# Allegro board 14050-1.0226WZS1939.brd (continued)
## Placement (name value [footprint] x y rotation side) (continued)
R144  100KR2J-1-GP  [R402H16]  42.58 25.78 0 top
R152  10KR2J-3-GP  [R402H16]  82.84 140.84 90 top
R154  10KR2J-3-GP  [R402H16]  71.66 141.86 270 top
R159  10KR2J-3-GP  [R402H16]  83.47 137.16 90 top
R160  10KR2J-3-GP  [R402H16]  71.66 140.84 90 top
R162  2K2R2J-2-GP  [R402H16]  82.33 143.51 0 top
R163  10KR2J-3-GP  [R402H16]  130.34 129.29 90 bottom
R165  10KR2J-3-GP  [R402H16]  131.86 128.78 0 bottom
R171  470KR2F-GP  [R402H16]  57.56 144.27 0 top
R172  1MR2J-1-GP  [R402H16]  57.18 138.56 90 top
R174  0R0402-PAD-2-GP  [0R0402-PAD-1]  55.28 139.57 270 top
R175  10KR2J-3-GP  [R402H16]  57.18 139.57 270 top
R178  1KR2J-1-GP  [R402H16]  49.44 136.78 270 top
R179  100KR2J-1-GP  [R402H16]  56.04 144.78 270 top
R181  100KR2J-1-GP  [R402H16]  56.04 143.76 90 top
R183  -  [0R0805-PAD]  7.53 190.88 0 bottom
R184  10KR2J-3-GP  [R402H16]  153.07 109.6 270 top
R185  -  [0R0805-PAD]  5.49 190.88 0 bottom
R202  2K1R2F-GP  [R402H16]  48.04 114.05 0 top
R203  2K1R2F-GP  [R402H16]  49.21 114.02 180 top
R205  0R0402-PAD-2-GP  [0R0402-PAD-1]  157.64 88.52 90 top
R206  0R2J-2-GP  [R402H16]  162.21 86.87 270 top
R207  0R0402-PAD-2-GP  [0R0402-PAD-1]  165.44 87.05 0 top
R208  47KR2F-GP  [R402H16]  166.91 87.5 270 top
R209  33R2J-2-GP  [R402H16]  159.11 83.11 270 bottom
R210  47KR2F-GP  [R402H16]  166.91 86.49 90 top
R212  68R2F-GP  [R402H16]  158.02 83.13 180 top
R213  10KR2J-3-GP  [R402H16]  166.15 84.96 0 top
R215  0R0603-PAD-2-GP-U  [0R0603-PAD-1-U]  176.69 82.68 0 top
R216  0R3J-0-U-GP  [R603H22]  174.15 82.68 0 top
R220  10R2F-L-GP  [R402H14]  170.39 83.31 0 top
R221  10KR2J-3-GP  [R402H16]  171.41 83.31 180 top
R222  0R0402-PAD-2-GP  [0R0402-PAD-1]  157.64 81.66 90 top
R223  2K2R2J-2-GP  [R402H16]  168.94 83.44 90 top
R225  1KR2J-1-GP  [R402H16]  170.85 81.53 270 top
R230  2K1R2F-GP  [R402H16]  49.18 108.33 0 top
R261  2K2R2J-2-GP  [R402H16]  160.18 71.75 270 top
R262  2K2R2J-2-GP  [R402H16]  162.09 71.75 270 top
R266  10KR2F-2-GP  [R402H16]  164.5 71.25 180 top
R267  5K1R2F-2-GP  [R402H16]  165.51 71.25 180 top
R268  20KR2F-L-GP  [R402H16]  166.53 71.25 0 top
R272  2K2R2J-2-GP  [R402H16]  160.18 70.74 270 top
R276  -  [0R0603-PAD]  160.94 48.13 0 bottom
R281  10KR2J-3-GP  [R402H16]  162.09 69.72 90 top
R284  10R2F-L-GP  [R402H14]  160.18 69.72 90 top
R287  1KR2J-1-GP  [R402H16]  31.53 33.02 270 top
R289  10KR2J-3-GP  [R402H16]  162.09 53.59 90 top
R294  10KR2J-3-GP  [R402H16]  156.12 45.72 0 bottom
R297  1KR2J-1-GP  [R402H16]  162.09 54.61 90 top
R299  243R2F-2-GP  [R402H16]  48.44 97.76 90 top
R300  0R0603-PAD-2-GP-U  [0R0603-PAD-1-U]  162.34 68.71 0 bottom
R301  0R0603-PAD-2-GP-U  [0R0603-PAD-1-U]  162.85 75.56 180 bottom
R302  5K11R2F-L1-GP  [R402H16]  80.68 85.72 180 bottom
R305  0R3J-0-U-GP  [R603H22]  162.21 48.13 180 bottom
R306  33R2J-2-GP  [R402H16]  162.09 55.63 90 top
R307  10KR2J-3-GP  [R402H16]  162.09 50.55 270 top
R308  10KR2J-3-GP  [R402H16]  162.09 58.67 90 top
R309  33R2J-2-GP  [R402H16]  162.09 59.69 270 top
R310  0R0402-PAD-2-GP  [0R0402-PAD-1]  157.26 64.14 180 top
R312  1KR2J-1-GP  [R402H16]  162.09 47.5 90 top
R313  10KR2J-3-GP  [R402H16]  163.61 45.97 180 top
R314  1KR2J-1-GP  [R402H16]  158.78 66.42 0 top
R316  10KR2J-3-GP  [R402H16]  162.09 44.45 90 top
R317  10KR2J-3-GP  [R402H16]  160.18 41.15 0 top
R319  100KR2F-L1-GP  [R402H16]  164.29 63.68 270 bottom
R320  243R2F-2-GP  [R402H16]  48.44 94.58 90 top
R322  1MR3F-GP  [R603H22]  163.96 62.59 90 bottom
R329  47KR2F-GP  [R402H16]  99.6 87.88 270 top
R334  10KR2J-3-GP  [R402H16]  157.13 41.15 0 top
R341  10KR2J-3-GP  [R402H16]  156.12 41.15 0 top
R344  0R0603-PAD-2-GP-U  [0R0603-PAD-1-U]  158.15 24.51 0 top
R345  0R0603-PAD-2-GP-U  [0R0603-PAD-1-U]  161.32 37.85 270 top
R346  0R0603-PAD-2-GP-U  [0R0603-PAD-1-U]  163.36 31.5 0 top
R347  3K9R2F-GP  [R402H16]  164.37 27.56 0 top
R350  10KR2J-3-GP  [R402H16]  160.82 88.77 90 top
R351  10KR2J-3-GP  [R402H16]  150.66 56.01 180 bottom
R352  33R2J-2-GP  [R402H16]  153.96 64.14 180 top
R353  100KR2J-1-GP  [R402H16]  152.94 64.14 0 top
R354  0R2J-2-GP  [R402H16]  98.71 91.19 90 top
R355  10K5R3F-GP  [R603H22]  161.32 35.31 270 top
R356  0R0603-PAD-2-GP-U  [0R0603-PAD-1-U]  161.32 36.58 90 top
R357  10KR2F-2-GP  [R402H16]  160.56 27.05 180 top
R358  5K6R2F-2-GP  [R402H16]  162.09 29.59 90 top
R359  0R0603-PAD-2-GP-U  [0R0603-PAD-1-U]  158.15 21.72 0 top
R360  100KR2J-1-GP  [R402H16]  160.94 34.16 90 top
R361  100KR2J-1-GP  [R402H16]  160.56 29.08 180 top
R364  10KR2J-3-GP  [R402H16]  138.72 59.56 90 top
R365  10K5R3F-GP  [R603H22]  155.48 21.72 0 top
R366  1KR2J-1-GP  [R402H16]  131.86 56.52 90 top
R367  0R0603-PAD-2-GP-U  [0R0603-PAD-1-U]  156.75 21.72 180 top
R368  20KR2J-L2-GP  [R402H16]  131.86 59.56 90 top
R369  1KR2J-1-GP  [R402H16]  131.86 58.55 90 top
R370  1KR2J-1-GP  [R402H16]  138.72 62.61 270 top
R371  100R2F-L1-GP-U  [R402H14]  138.72 60.58 270 top
R372  0R0402-PAD-2-GP  [0R0402-PAD-1]  138.72 54.48 270 top
R373  0R0402-PAD-2-GP  [0R0402-PAD-1]  138.72 53.47 270 top
R374  0R0402-PAD-2-GP  [0R0402-PAD-1]  138.72 52.45 90 top
R375  0R0402-PAD-2-GP  [0R0402-PAD-1]  138.72 58.55 270 top
R376  10R3J-3-GP  [R603H22]  155.23 36.58 0 top
R377  1KR2J-1-GP  [R402H16]  27.64 6.17 0 bottom
R378  8K2R2J-3-GP  [R402H16]  33.31 5.59 270 top
R379  0R2J-2-GP  [R402H16]  138.72 57.53 90 top
R380  1KR2J-1-GP  [R402H16]  134.4 55.37 90 top
R381  10KR2J-3-GP  [R402H16]  134.91 61.21 270 top
R382  10KR2J-3-GP  [R402H16]  136.81 52.45 90 top
R383  0R0402-PAD-2-GP  [0R0402-PAD-1]  154.34 24.89 0 top
R384  1KR2J-1-GP  [R402H16]  134.91 60.2 270 top
R385  0R0402-PAD-2-GP  [0R0402-PAD-1]  138.72 55.5 90 top
R388  8K45R2F-2-GP  [R402H16]  95.33 102.06 270 bottom
R389  10KR5F-2-GP  [R805H24]  33.05 18.54 90 bottom
R391  2K2R2J-2-GP  [R402H16]  100.11 89.41 180 top
R394  2KR2F-3-GP  [R402H16]  92.87 101.6 180 bottom
R396  3D3R3F-GP  [R603H22]  142.27 17.14 270 top
R397  10KR2F-2-GP  [R402H16]  146.69 50.5 90 bottom
R398  10KR2J-L-GP  [R402H15]  79.15 83.31 270 bottom
R399  0R0402-PAD-2-GP  [0R0402-PAD-1]  146.69 51.54 270 bottom
R400  0R0402-PAD-2-GP  [0R0402-PAD-1]  146.69 48.39 270 bottom
R403  3D3R3F-GP  [R603H22]  144.94 17.14 90 top
R404  10KR2F-2-GP  [R402H16]  146.69 49.45 90 bottom
R406  1KR2J-1-GP  [R402H16]  32.8 8 180 bottom
R407  1MR3F-GP  [R603H22]  36.74 9.27 270 top
R412  2K49R2F-GP  [R402H16]  39.28 9.65 180 top
R413  0R2J-2-GP  [R402H16]  37.5 20.07 180 top
R415  3D3R3F-GP  [R603H22]  150.4 17.14 90 top
R419  3D3R3F-GP  [R603H22]  147.73 17.14 270 top
R428  47R2J-2-GP  [R402H16]  82.58 36.2 180 top
R429  47R2J-2-GP  [R402H16]  83.68 36.17 180 top
R433  1KR2J-1-GP  [R402H16]  107.98 16.89 90 top
R481  10KR2J-3-GP  [R402H16]  42.32 104.52 270 bottom
R482  10KR2J-3-GP  [R402H16]  44.48 95 180 bottom
R483  10KR2J-3-GP  [R402H16]  42.07 115.44 90 top
R484  100R2F-L1-GP-U  [R402H14]  42.2 111.89 270 bottom
R495  300R2J-4-GP  [R402H16]  85 190.63 0 top
R501  100KR2J-1-GP  [R402H16]  36.23 105.41 180 bottom
R502  0R0402-PAD-2-GP  [0R0402-PAD-1]  37.24 105.41 0 bottom
R503  0R2J-2-GP  [R402H16]  35.16 105.41 180 bottom
R504  100KR2J-1-GP  [R402H16]  96.17 223.9 180 top
R507  0R0402-PAD-2-GP  [0R0402-PAD-1]  31.53 99.75 270 bottom
R508  4K7R2J-2-GP  [R402H16]  20.23 220.73 90 top
R510  1KR2J-1-GP  [R402H16]  31.53 89.15 90 bottom
R511  12KR2F-L-GP  [R402H16]  31.53 98.73 90 bottom
R512  100KR2J-1-GP  [R402H16]  31.53 87.12 90 bottom
R513  100KR2J-1-GP  [R402H16]  44.23 79.17 90 top
R514  10KR2J-3-GP  [R402H16]  48.17 73 90 top
R515  0R0402-PAD-2-GP  [0R0402-PAD-1]  49.69 73.58 180 top
R517  10KR2J-3-GP  [R402H16]  31.53 90.17 270 bottom
R523  10KR2J-3-GP  [R402H16]  48.57 76.45 0 bottom
R524  10KR2J-3-GP  [R402H16]  41.44 80.34 180 bottom
R526  4K7R2J-2-GP  [R402H16]  17.86 220.17 270 top
R527  4K7R2J-2-GP  [R402H16]  15.4 220.85 270 bottom
R528  0R0402-PAD-2-GP  [0R0402-PAD-1]  73.82 190.63 180 top
R529  0R0402-PAD-2-GP  [0R0402-PAD-1]  74.84 190.63 180 top
R530  10KR2J-3-GP  [R402H16]  31.53 88.14 90 bottom
R531  10KR2J-3-GP  [R402H16]  46.46 73.48 0 top
R533  10KR2J-3-GP  [R402H16]  44.97 74.09 270 top
R535  4K7R2J-2-GP  [R402H16]  44.23 78.05 90 top
R536  0R0402-PAD-2-GP  [0R0402-PAD-1]  44.97 73.05 270 top
R542  1KR2J-1-GP  [R402H16]  45.37 127.38 270 top
R545  1KR2J-1-GP  [R402H16]  80.93 190.63 180 top
R557  1KR2F-3-GP  [R402H16]  59.09 174.24 180 top
R558  1K69R2F-2-GP  [R402H16]  58.07 174.24 0 top
R559  1KR2F-3-GP  [R402H16]  59.09 169.93 0 top
R568  0R0402-PAD-2-GP  [0R0402-PAD-1]  56.8 171.83 90 top
R570  10R2F-L-GP  [R402H14]  65.44 144.15 270 top
R571  10R2F-L-GP  [R402H14]  66.96 143.38 0 top
R576  0R0402-PAD-2-GP  [0R0402-PAD-1]  69.25 143.38 0 top
R582  10KR2J-3-GP  [R402H16]  62.26 155.7 270 top
R584  10R2F-L-GP  [R402H14]  63.03 145.8 0 top
R585  10R2F-L-GP  [R402H14]  65.44 145.16 270 top
R586  1KR2F-3-GP  [R402H16]  65.44 147.32 90 top
R617  33KR2J-3-GP  [R402H16]  165.18 85.45 180 bottom
R618  0R2J-2-GP  [R402H16]  158.02 87 0 bottom
R627  1KR2J-1-GP  [R402H16]  166.53 73.91 270 bottom
R634  4K7R2J-2-GP  [R402H16]  137.93 30.02 0 top
R635  1KR2J-1-GP  [R402H16]  138.31 31.5 90 top
R636  10KR2J-3-GP  [R402H16]  138.97 30.02 0 top
R637  10KR2J-3-GP  [R402H16]  143.95 29.21 180 top
R638  0R0402-PAD-2-GP  [0R0402-PAD-1]  147.78 34.92 90 top
R639  20KR2J-L2-GP  [R402H16]  146.51 33.43 180 top
R643  20KR2J-L2-GP  [R402H16]  147 31.5 0 top
R644  10KR2F-2-GP  [R402H16]  120.25 47.75 270 top
R645  10KR2F-2-GP  [R402H16]  131.68 48.01 90 top
R650  10KR2F-2-GP  [R402H16]  120.25 49.78 270 top
R651  0R0402-PAD-2-GP  [0R0402-PAD-1]  140.62 51.92 0 bottom
R655  10KR2F-2-GP  [R402H16]  120.25 50.8 270 top
R656  20KR2J-L2-GP  [R402H16]  152.81 50.03 90 bottom
R657  100KR2J-1-GP  [R402H16]  152.81 51.05 270 bottom
R658  10KR2F-2-GP  [R402H16]  142.88 50.42 90 bottom
R666  0R0402-PAD-2-GP  [0R0402-PAD-1]  156.88 31.5 90 bottom
R668  10KR2J-3-GP  [R402H16]  159.04 39.24 180 top
R674  0R0402-PAD-2-GP  [0R0402-PAD-1]  158.15 41.15 0 top
R675  10KR2J-3-GP  [R402H16]  159.16 41.15 0 top
R679  1KR2J-1-GP  [R402H16]  162.09 60.73 90 top
R680  10KR2J-3-GP  [R402H16]  156.24 64.14 180 top
R682  10KR2J-3-GP  [R402H16]  162.09 56.64 270 top
R683  10KR2J-3-GP  [R402H16]  149.89 64.26 0 top
R689  6K49R2F-1-GP  [R402H16]  139.1 47.12 90 bottom
R702  10KR2F-2-GP  [R402H16]  145.83 64.26 0 top
R707  0R0402-PAD-2-GP  [0R0402-PAD-1]  138.72 61.59 270 top
R709  0R0402-PAD-2-GP  [0R0402-PAD-1]  139.58 51.92 0 bottom
R715  0R2J-2-GP  [R402H16]  139.73 64.39 0 top
R716  0R2J-2-GP  [R402H16]  140.75 64.39 0 top
R717  10KR2J-3-GP  [R402H16]  66.96 135.76 180 top
R718  15KR2F-GP  [R402H16]  38.01 144.53 0 top
R722  1MR2J-1-GP  [R402H16]  35.21 140.21 90 top
R723  0R0402-PAD-2-GP  [0R0402-PAD-1]  28.56 14.45 180 top
R724  165R3F-GP  [R603H22]  28.35 19.94 270 bottom
R729  0R2J-2-GP  [R402H16]  25.05 16.13 90 bottom
R730  165R3F-GP  [R603H22]  25.69 21.21 270 bottom
R731  4K7R2J-2-GP  [R402H16]  24.67 26.67 180 bottom
R732  100KR2J-1-GP  [R402H16]  40.04 139.32 0 top
R733  100KR2J-1-GP  [R402H16]  40.04 141.22 0 top
R735  165R3F-GP  [R603H22]  25.69 19.94 90 bottom
R742  1KR2F-3-GP  [R402H16]  34.58 25.78 90 top
R743  33R2J-2-GP  [R402H16]  32.67 22.61 270 top
R744  -  [0R0402-PAD]  34.96 24.77 90 top
R755  4K7R2J-2-GP  [R402H16]  33.43 28.07 0 top
R758  33R2J-2-GP  [R402H16]  31.4 28.07 0 top
R762  15KR2F-GP  [R402H16]  106.59 29.59 0 top
R764  10KR2J-3-GP  [R402H16]  49.82 5.97 0 bottom
R774  10KR2J-3-GP  [R402H16]  44.23 7.87 180 bottom
R775  8K2R2J-3-GP  [R402H16]  47.02 9.4 90 top
R776  39K2R2F-L-GP  [R402H16]  45.25 7.87 0 top
R777  1KR2J-1-GP  [R402H16]  60.74 157.99 180 top
R870  243R2F-2-GP  [R402H16]  48.42 111.38 270 bottom
R885  2K1R2F-GP  [R402H16]  49.18 108.33 180 bottom
R886  2K1R2F-GP  [R402H16]  47.15 108.33 0 bottom
R899  243R2F-2-GP  [R402H16]  48.7 106.78 270 bottom
R924  2K1R2F-GP  [R402H16]  63.2 104.52 0 bottom
R928  2K1R2F-GP  [R402H16]  62.19 104.52 180 bottom
R935  4K53R2F-1-GP  [R402H16]  99.86 101.73 180 top
R940  2KR2F-3-GP  [R402H16]  102.14 101.73 0 top
R943  8K45R2F-2-GP  [R402H16]  95.33 103.2 270 bottom
R945  2K1R2F-GP  [R402H16]  48.93 96.27 0 bottom
R946  2K1R2F-GP  [R402H16]  47.79 96.27 180 bottom
R948  4K75R2F-1-GP  [R402H16]  92.92 103.59 0 bottom
R963  10KR2J-L-GP  [R402H15]  81.06 83.57 270 bottom
R1074  100KR2J-1-GP  [R402H16]  31.53 91.19 90 bottom
R1079  100KR2J-1-GP  [R402H16]  31.53 94.11 270 bottom
R1126  165KR2F-GP  [R402H16]  162.85 90.22 180 top
R1129  8K2R2J-3-GP  [R402H16]  165.23 88.95 270 top
R1154  0R2J-2-GP  [R402H16]  106.71 203.58 270 top
R1155  0R2J-2-GP  [R402H16]  104.17 218.19 270 top
R1158  1KR2F-3-GP  [R402H16]  81.87 92.71 90 bottom
R1159  10KR2J-L-GP  [R402H15]  99.42 106.66 0 top
R1160  -  [0R0402-PAD]  98.35 106.79 0 top
R1161  1K69R2F-2-GP  [R402H16]  96.32 107.17 0 bottom
R1162  1KR2F-3-GP  [R402H16]  95.31 107.17 0 bottom
R1163  1KR2F-3-GP  [R402H16]  42.32 106.55 270 bottom
R1164  100KR2J-1-GP  [R402H16]  108.75 92.96 270 top
R1165  0R0402-PAD-2-GP  [0R0402-PAD-1]  98.74 96.37 270 top
R1166  0R0402-PAD-2-GP  [0R0402-PAD-1]  98.74 95.36 270 top
R1167  10KR2J-3-GP  [R402H16]  108.75 77.09 270 top
R1168  33R2J-2-GP  [R402H16]  108.11 79.12 270 top
R1169  33R2J-2-GP  [R402H16]  107.48 80.39 270 top
R1170  33R2J-2-GP  [R402H16]  97.19 83.06 270 top
R1171  33R2J-2-GP  [R402H16]  97.19 84.33 270 top
R1178  10KR2J-3-GP  [R402H16]  40.8 130.05 0 top
R1179  1KR2J-1-GP  [R402H16]  41.44 128.14 180 top
R1180  0R2J-2-GP  [R402H16]  48.8 5.97 180 bottom
R1182  0R0603-PAD-2-GP-U  [0R0603-PAD-1-U]  85 42.8 90 bottom
R1183  10KR2J-3-GP  [R402H16]  40.67 5.97 0 top
R1184  0R2J-2-GP  [R402H16]  59.22 148.84 270 top
R1185  10KR2J-3-GP  [R402H16]  93.63 14.86 180 bottom
R1186  10KR2J-3-GP  [R402H16]  88.43 17.14 0 top
R1188  10KR2J-3-GP  [R402H16]  162.09 52.58 90 top
R1193  0R0603-PAD-2-GP-U  [0R0603-PAD-1-U]  173.39 84.07 90 bottom
R1194  10KR2J-3-GP  [R402H16]  40.67 7.87 0 top
R1195  39K2R2F-L-GP  [R402H16]  163.69 92.15 0 top
R1199  0R0402-PAD-2-GP  [0R0402-PAD-1]  158.02 39.24 180 top
R1200  40D2R2F-GP  [R402H16]  77.1 115.49 0 top
R1201  120R2F-GP  [R402H16]  79.81 110.22 180 bottom
R1202  10R2F-L-GP  [R402H14]  84.13 89.9 180 bottom
R1203  0R0402-PAD-2-GP  [0R0402-PAD-1]  152.81 18.03 270 top
R1204  2K2R2J-2-GP  [R402H16]  85.17 87.99 180 bottom
R1205  4K99R2F-L-GP  [R402H16]  83.11 89.9 180 bottom
R1206  51D1R2F-GP  [R402H16]  78.16 81.89 0 top
R1207  51D1R2F-GP  [R402H16]  77.15 81.89 0 top
R1209  0R0402-PAD-2-GP  [0R0402-PAD-1]  106.71 204.6 270 top
R1210  249R2F-GP  [R402H16]  93.45 97.08 0 bottom
R1211  499R2F-2-GP  [R402H16]  94.47 97.08 180 bottom
R1584  1KR2J-1-GP  [R402H16]  96.05 161.04 270 bottom
R1585  0R2J-2-GP  [R402H16]  108.62 156.46 0 bottom
R1586  1KR2J-1-GP  [R402H16]  107.48 156.46 0 bottom
R1588  1KR2F-3-GP  [R402H16]  95.28 165.35 270 bottom
R1592  36R3F-GP  [R603H22]  132.75 43.94 0 top
R1593  4K7R2F-GP  [R402H16]  131.72 41.54 0 top
R1594  4K7R2F-GP  [R402H16]  126.91 42.55 0 top
R1595  0R3J-0-U-GP  [R603H22]  87.16 136.4 180 top
R1596  4K7R2F-GP  [R402H16]  131.85 29.6 180 top
R1598  4K7R2F-GP  [R402H16]  133.75 41.54 0 top
R1601  0R0603-PAD-2-GP-U  [0R0603-PAD-1-U]  88.43 136.4 0 top
R1603  2KR2F-3-GP  [R402H16]  72.17 186.56 180 top
R1604  1KR2J-1-GP  [R402H16]  71.15 186.56 180 top
R1605  1KR2J-1-GP  [R402H16]  74.2 186.56 180 top
R1606  1KR2J-1-GP  [R402H16]  73.19 186.56 180 top
R1607  1KR2J-1-GP  [R402H16]  75.22 186.56 180 top
R1608  1KR2J-1-GP  [R402H16]  77.88 186.56 180 top
R1609  1KR2J-1-GP  [R402H16]  76.87 186.56 180 top
R1610  1KR2J-1-GP  [R402H16]  81.95 190.63 180 top
R1611  0R0402-PAD-2-GP  [0R0402-PAD-1]  75.85 190.63 180 top
R1612  0R0402-PAD-2-GP  [0R0402-PAD-1]  69.76 190.63 180 top
R1613  0R0402-PAD-2-GP  [0R0402-PAD-1]  76.87 190.63 180 top
R1614  1KR2J-1-GP  [R402H16]  82.96 186.56 0 top
R1615  1KR2J-1-GP  [R402H16]  78.9 194.69 0 top
R1616  1KR2J-1-GP  [R402H16]  83.98 194.69 0 top
R1617  300R2J-4-GP  [R402H16]  79.92 186.56 0 top
R1618  1KR2J-1-GP  [R402H16]  77.88 197.99 180 top
R1619  1KR2J-1-GP  [R402H16]  76.87 197.99 180 top
R1620  0R2J-2-GP  [R402H16]  122.08 218.44 270 top
R1621  0R2J-2-GP  [R402H16]  122.08 217.42 270 top
R1622  0R2J-2-GP  [R402H16]  122.08 219.46 270 top
R1623  300R2J-4-GP  [R402H16]  88.04 190.63 180 top
R1628  1KR2J-1-GP  [R402H16]  79.92 190.63 180 top
R1629  0R2J-2-GP  [R402H16]  77.88 190.63 0 top
R1630  1KR2J-1-GP  [R402H16]  86.01 194.69 180 top
R1631  0R2J-2-GP  [R402H16]  88.04 194.69 0 top
R1632  1KR2J-1-GP  [R402H16]  80.93 186.56 180 top
R1633  1KR2F-3-GP  [R402H16]  142.4 191.9 180 bottom
R1634  10KR2J-3-GP  [R402H16]  131.61 126.24 270 bottom
R1635  10KR2J-3-GP  [R402H16]  133.51 126.24 270 bottom
R1644  1KR2F-3-GP  [R402H16]  64.8 148.46 90 top
R1645  22R2J-2-GP  [R402H16]  76.82 147.19 180 bottom
R1646  22R2J-2-GP  [R402H16]  80.93 137.16 270 top
R1647  0R0402-PAD-2-GP  [0R0402-PAD-1]  78.39 150.88 180 bottom
R1648  11K8R2F-GP  [R402H16]  71.79 154.56 90 bottom
R1649  1KR2F-3-GP  [R402H16]  65.44 170.43 270 top
R1650  1KR2J-1-GP  [R402H16]  65.44 143.13 90 top
R1653  0R0402-PAD-2-GP  [0R0402-PAD-1]  56.8 162.69 90 top
R1654  0R0402-PAD-2-GP  [0R0402-PAD-1]  62.26 154.69 90 top
R1657  1KR2F-3-GP  [R402H16]  74.2 142.11 0 top
R1658  15KR2F-GP  [R402H16]  56.68 163.7 90 top
R1659  10KR2J-3-GP  [R402H16]  84.74 141.86 90 top
R1660  10KR2J-3-GP  [R402H16]  84.74 140.84 270 top
R1661  10KR2J-3-GP  [R402H16]  75.22 142.11 180 top
R1662  10KR2J-3-GP  [R402H16]  82.84 141.86 270 top
R1663  10KR2J-3-GP  [R402H16]  76.23 142.11 0 top
R1664  1KR2J-1-GP  [R402H16]  56.68 164.72 90 top
R1665  1KR2J-1-GP  [R402H16]  56.8 161.67 90 top
R1666  1KR2J-1-GP  [R402H16]  62.26 157.73 90 top
R1668  0R0402-PAD-2-GP  [0R0402-PAD-1]  60.87 137.79 270 top
R1669  2K2R2J-2-GP  [R402H16]  80.3 143.51 0 top
R1670  10KR2J-3-GP  [R402H16]  60.1 153.67 90 top
R1671  20MR3-GP  [R603H22]  64.8 150.88 0 top
R1672  10KR2J-3-GP  [R402H16]  73.52 51.59 270 top
R1673  2K2R2J-2-GP  [R402H16]  84.36 143.51 0 top
R1674  10KR2J-3-GP  [R402H16]  83.35 143.51 0 top
R1675  2K2R2J-2-GP  [R402H16]  56.68 165.74 270 top
R1676  2K2R2J-2-GP  [R402H16]  62.26 156.72 270 top
R1677  47KR2J-2-GP  [R402H16]  52.36 157.86 90 top
R1678  33R2J-2-GP  [R402H16]  56.29 148.84 90 top
R1679  10KR2J-3-GP  [R402H16]  56.8 156.59 270 top
R1683  10KR2J-3-GP  [R402H16]  75.85 49.2 180 top
R1684  10KR2J-3-GP  [R402H16]  70.26 143.38 180 top
R1685  10KR2J-3-GP  [R402H16]  71.28 143.38 0 top
R1686  10R2F-L-GP  [R402H14]  67.98 143.38 0 top
R1687  10KR2J-3-GP  [R402H16]  83.47 138.18 270 top
R1688  10KR2J-3-GP  [R402H16]  83.47 139.19 90 top
R1690  15KR2F-GP  [R402H16]  56.8 160.66 90 top
R1691  15KR2F-GP  [R402H16]  62.26 158.75 90 top
R1696  39D2R2F-L-GP  [R402H16]  94.14 162.69 270 bottom
R1697  0R0402-PAD-2-GP  [0R0402-PAD-1]  86.01 186.56 0 top
R1698  0R0402-PAD-2-GP  [0R0402-PAD-1]  96.17 221.87 0 top
R1699  4K7R2J-2-GP  [R402H16]  115.35 59.56 270 top
R1700  10KR2J-3-GP  [R402H16]  117.25 59.56 90 top
R1701  10KR2J-3-GP  [R402H16]  91.35 222 0 top
R1702  10KR2J-3-GP  [R402H16]  100.11 214.38 90 top
R1703  10KR2J-3-GP  [R402H16]  100.11 215.65 90 top
R1704  1KR2J-1-GP  [R402H16]  100.11 209.3 90 top
R1705  10KR2J-3-GP  [R402H16]  100.11 216.92 90 top
R1707  10KR2J-3-GP  [R402H16]  122.08 204.98 90 top
R1708  0R5J-5-GP  [R805H24]  127.8 205.99 180 bottom
R1709  0R0402-PAD-2-GP  [0R0402-PAD-1]  104.17 217.17 270 top
R1710  0R2J-2-GP  [R402H16]  122.08 216.41 270 top
R1711  0R0402-PAD-2-GP  [0R0402-PAD-1]  104.17 213.11 270 top
R1712  0R0402-PAD-2-GP  [0R0402-PAD-1]  104.17 214.12 270 top
R1713  0R0402-PAD-2-GP  [0R0402-PAD-1]  104.17 211.07 270 top
R1714  0R0402-PAD-2-GP  [0R0402-PAD-1]  104.17 212.09 270 top
R1716  10KR2J-3-GP  [R402H16]  130 217.96 90 top
R1717  0R2J-2-GP  [R402H16]  122.08 221.49 270 top
R1718  0R0402-PAD-2-GP  [0R0402-PAD-1]  122.08 223.52 270 top
R1719  0R0402-PAD-2-GP  [0R0402-PAD-1]  104.17 220.22 270 top
R1720  1KR2J-1-GP  [R402H16]  86.01 190.63 180 top
R1721  1KR2F-3-GP  [R402H16]  161.2 111 90 top
R1724  10KR2J-3-GP  [R402H16]  56.8 168.78 270 top
R1725  10KR2J-3-GP  [R402H16]  105.57 29.59 180 top
R1727  15KR2F-GP  [R402H16]  174.15 125.73 0 top
R1728  10KR2J-3-GP  [R402H16]  173.13 125.73 180 top
R1729  1KR2J-1-GP  [R402H16]  169.71 126.36 90 top
R1730  1KR2J-1-GP  [R402H16]  31.53 35.05 270 top
R1731  10KR2J-3-GP  [R402H16]  31.53 32 270 top
R1732  1KR2J-1-GP  [R402H16]  31.53 29.97 270 top
R1733  10KR2J-3-GP  [R402H16]  31.53 30.99 270 top
R1734  10KR2J-3-GP  [R402H16]  31.53 34.04 270 top
R1735  10R2F-L-GP  [R402H14]  65.44 146.18 270 top
R1736  10KR2J-3-GP  [R402H16]  34.45 135.76 0 top
R1737  10KR2J-3-GP  [R402H16]  35.72 119.89 180 top
R1738  10KR2J-3-GP  [R402H16]  36.99 135.76 0 top
R1739  0R0402-PAD-2-GP  [0R0402-PAD-1]  33.18 119.89 0 top
R1740  0R0402-PAD-2-GP  [0R0402-PAD-1]  35.72 135.76 0 top
R1741  0R0402-PAD-2-GP  [0R0402-PAD-1]  35.34 117.6 90 top
R1743  33R2J-2-GP  [R402H16]  100.11 213.11 90 top
R1744  0R0402-PAD-2-GP  [0R0402-PAD-1]  89.44 213.11 270 top
R1745  0R0402-PAD-2-GP  [0R0402-PAD-1]  89.44 214.38 270 top
R1746  0R0402-PAD-2-GP  [0R0402-PAD-1]  89.44 216.92 270 top
R1747  0R0402-PAD-2-GP  [0R0402-PAD-1]  89.44 218.19 270 top
R1748  0R0402-PAD-2-GP  [0R0402-PAD-1]  89.44 219.46 270 top
R1749  10KR2J-3-GP  [R402H16]  87.66 143.38 0 top
R1751  165R3F-GP  [R603H22]  28.35 18.54 270 bottom
R1752  4K7R2J-2-GP  [R402H16]  30.64 16.13 270 top
R1753  10KR2J-3-GP  [R402H16]  25.18 28.7 90 bottom
R1754  10KR2J-3-GP  [R402H16]  28.99 29.72 270 bottom
R1755  33R2J-2-GP  [R402H16]  32.04 24.26 0 top
R1756  33R2J-2-GP  [R402H16]  27.85 26.67 0 bottom
R1757  10KR2J-3-GP  [R402H16]  36.61 28.57 0 top
R1758  4K7R2J-2-GP  [R402H16]  33.05 26.16 0 top
R1759  10KR2J-3-GP  [R402H16]  29.88 25.15 90 bottom
R1760  10KR2F-2-GP  [R402H16]  26.83 26.67 180 bottom
R1761  0R2J-2-GP  [R402H16]  28.48 17.4 90 bottom
R1762  0R0402-PAD-2-GP  [0R0402-PAD-1]  106.46 8.51 90 top
R1763  0R2J-2-GP  [R402H16]  16.92 159.13 180 bottom
R1764  0R2J-2-GP  [R402H16]  17.94 159.13 0 bottom
R1767  1K5R3-GP  [R603H22]  93.89 7.24 0 top
R1774  0R2J-2-GP  [R402H16]  62.64 148.89 90 top
R1776  47KR2F-GP  [R402H16]  60.23 143.51 270 top
R1777  470KR2F-GP  [R402H16]  91.6 19.56 180 top
R1778  470KR2F-GP  [R402H16]  35.21 141.22 90 top
R1779  1MR2J-1-GP  [R402H16]  91.6 21.46 180 top
R1780  100KR2J-1-GP  [R402H16]  90.58 19.56 180 top
R1781  100KR2J-1-GP  [R402H16]  90.08 21.08 270 top
R1782  4K7R2J-2-GP  [R402H16]  90.08 22.1 90 top
R1783  10KR2J-3-GP  [R402H16]  94.78 23.62 270 top
R1784  0R3J-0-U-GP  [R603H22]  161.73 188.77 90 bottom
R1785  10KR2J-3-GP  [R402H16]  29.62 14.1 0 top
R1808  10KR2F-2-GP  [R402H16]  142.65 72.39 180 top
R1809  10KR2F-2-GP  [R402H16]  141.38 72.39 180 top
R1810  0R2J-2-GP  [R402H16]  142.02 73.91 90 top
R1813  20KR2F-L-GP  [R402H16]  56.8 169.8 270 top
R1816  2KR2F-3-GP  [R402H16]  31.78 8 0 bottom
R1817  15KR2F-GP  [R402H16]  31.4 5.59 90 top
R1819  10KR2J-3-GP  [R402H16]  40.29 9.78 0 top
R1823  10KR2F-2-GP  [R402H16]  131.73 46.86 90 top
R1824  10KR2F-2-GP  [R402H16]  131.68 49.15 90 top
R1825  10KR2J-3-GP  [R402H16]  143.8 64.26 180 top
R1826  10KR2J-3-GP  [R402H16]  162.09 57.66 90 top
R1829  10KR2J-3-GP  [R402H16]  155.1 41.15 0 top
R1830  10KR2F-2-GP  [R402H16]  139.73 45.59 0 top
R1831  4K7R2J-2-GP  [R402H16]  152.69 43.94 0 bottom
R1832  10KR2F-2-GP  [R402H16]  138.84 41.4 90 top
R1833  17K8R2F-GP  [R402H16]  135.92 45.09 0 top
R1834  10KR2F-2-GP  [R402H16]  147.35 56.77 180 bottom
R1835  10KR2F-2-GP  [R402H16]  139.1 48.13 90 bottom
R1837  1KR2J-1-GP  [R402H16]  138.72 50.55 0 top
R1838  17K8R2F-GP  [R402H16]  139.1 47.12 270 top
R1840  10KR2J-3-GP  [R402H16]  144.81 64.26 180 top
R1841  10KR2F-2-GP  [R402H16]  139.1 48.13 270 top
R1842  0R0402-PAD-2-GP  [0R0402-PAD-1]  156.12 47.75 180 bottom
R1843  2K2R2J-2-GP  [R402H16]  146.85 62.48 270 bottom
R1844  4K7R2J-2-GP  [R402H16]  133.38 50.8 180 top
R1845  10KR2J-3-GP  [R402H16]  152.69 56.01 180 bottom
R1846  1K5R3-GP  [R603H22]  60.18 34.74 0 bottom
R1847  100KR3F-L-GP  [R603H22]  66.33 32.38 90 top
R1848  10KR3J-L1-GP  [R603H22]  64.42 44.07 180 top
R1849  10KR2J-3-GP  [R402H16]  53.45 37.16 180 bottom
R1850  56KR3F-GP  [R603H22]  67.85 30.35 0 top
R1851  33R2J-2-GP  [R402H16]  60.18 37.03 180 bottom
R1852  100KR2J-1-GP  [R402H16]  54.47 35.25 180 bottom
R1853  15KR2F-GP  [R402H16]  53.45 35.25 180 bottom
R1857  0R0402-PAD-2-GP  [0R0402-PAD-1]  131.86 57.53 270 top
R1858  0R0402-PAD-2-GP  [0R0402-PAD-1]  36.1 86.49 0 bottom
R1860  4K7R2J-2-GP  [R402H16]  30.26 77.29 180 bottom
R1861  0R2J-2-GP  [R402H16]  72.8 192.41 270 top
R1863  1KR2J-1-GP  [R402H16]  162.09 45.47 90 top
R1864  1KR2J-1-GP  [R402H16]  162.09 51.56 90 top
R1867  2KR2J-1-GP  [R402H16]  80.93 136.14 270 top
R1868  10KR2J-3-GP  [R402H16]  83.47 136.14 270 top
R1869  2KR2J-1-GP  [R402H16]  80.17 138.81 90 top
R1870  10KR2J-3-GP  [R402H16]  78.27 140.08 90 top
R1871  2KR2J-1-GP  [R402H16]  75.47 139.32 90 top
R1872  10KR2J-3-GP  [R402H16]  75.47 140.34 270 top
R1873  2KR2J-1-GP  [R402H16]  54.9 168.78 90 top
R1874  100KR2J-1-GP  [R402H16]  55.15 166.24 180 top
R1875  10KR2J-3-GP  [R402H16]  73.57 139.32 90 top
R1876  10KR2J-3-GP  [R402H16]  80.17 140.84 270 top
R1877  10KR2J-3-GP  [R402H16]  83.47 135.13 270 top
R1878  0R2J-2-GP  [R402H16]  141.94 10.21 270 top
R1879  1MR3F-GP  [R603H22]  98.48 109.71 180 top
R1880  10KR2J-3-GP  [R402H16]  104.17 101.73 0 top
R1881  10KR2J-3-GP  [R402H16]  103.16 101.73 0 top
R1882  10KR2J-3-GP  [R402H16]  81.59 82.02 180 top
R1883  4K7R2J-2-GP  [R402H16]  98.99 105.19 270 top
R1884  33R2J-2-GP  [R402H16]  97.06 89.41 180 top
R1885  10KR2J-3-GP  [R402H16]  97.57 87.88 270 top
R1886  10KR2J-3-GP  [R402H16]  81.59 83.93 0 top
R1887  10KR2J-3-GP  [R402H16]  98.08 89.41 180 top
R1888  100R2F-L1-GP-U  [R402H14]  79.03 112.27 270 bottom
R1889  100R2F-L1-GP-U  [R402H14]  74.71 113.28 90 bottom
R1890  40D2R2F-GP  [R402H16]  78.16 115.49 0 top
R1891  47R2J-2-GP  [R402H16]  84.14 87.99 180 bottom
R1892  10KR2J-L-GP  [R402H15]  76.61 82.3 180 bottom
R1893  10KR2J-L-GP  [R402H15]  77.63 82.3 180 bottom
R1894  1KR2J-1-GP  [R402H16]  101.13 87.5 0 top
R1895  10KR2J-L-GP  [R402H15]  75.6 82.3 180 bottom
R1896  47KR2F-GP  [R402H16]  99.09 89.41 180 top
R1897  1KR2F-3-GP  [R402H16]  82.61 83.93 180 bottom
R1899  4K75R2F-1-GP  [R402H16]  98.33 100.2 90 top
R1900  8K45R2F-2-GP  [R402H16]  98.33 101.22 90 top
R1901  0R0402-PAD-2-GP  [0R0402-PAD-1]  81.95 186.56 180 top
R1902  0R0402-PAD-2-GP  [0R0402-PAD-1]  78.9 190.63 180 top
R1903  0R0402-PAD-2-GP  [0R0402-PAD-1]  87.03 194.69 180 top
R1904  0R0402-PAD-2-GP  [0R0402-PAD-1]  87.03 190.63 180 top
R1905  2K1R2F-GP  [R402H16]  47.02 108.33 180 top
R1906  40D2R2F-GP  [R402H16]  48.7 111.26 270 top
R1907  40D2R2F-GP  [R402H16]  48.7 112.37 270 top
R1908  40D2R2F-GP  [R402H16]  48.44 92.81 270 top
R1909  40D2R2F-GP  [R402H16]  48.44 91.66 270 top
R1910  2K1R2F-GP  [R402H16]  48.8 96.14 180 top
R1911  2K1R2F-GP  [R402H16]  46.77 96.14 0 top
R1912  0R0402-PAD-2-GP  [0R0402-PAD-1]  95.28 169.8 0 bottom
R1914  100KR2J-1-GP  [R402H16]  107.48 95.5 180 top
R1915  10KR2J-3-GP  [R402H16]  110.65 90.68 270 top
R1916  0R0402-PAD-2-GP  [0R0402-PAD-1]  108.66 90.67 270 top
R1917  1KR2J-1-GP  [R402H16]  106.97 88.52 0 top
R1918  470KR2F-GP  [R402H16]  110.78 92.96 90 top
R1919  1MR2J-1-GP  [R402H16]  111.54 91.82 90 top
R1920  0R2J-2-GP  [R402H16]  98.71 92.2 90 top
R1921  2K1R2F-GP  [R402H16]  48.29 91.19 0 bottom
R1922  2K1R2F-GP  [R402H16]  49.31 91.19 180 bottom
R1923  2K1R2F-GP  [R402H16]  48.44 93.82 270 bottom
R1924  2K1R2F-GP  [R402H16]  48.31 92.81 90 bottom
R1925  0R2J-2-GP  [R402H16]  122.08 222.5 270 top
R1926  10KR2J-3-GP  [R402H16]  86.65 143.38 0 top
R1930  0R2J-2-GP  [R402H16]  24.04 139.57 0 top
R1931  0R2J-2-GP  [R402H16]  104.17 219.2 270 top
R1932  10KR2J-3-GP  [R402H16]  101 222 0 top
R1933  10KR2J-3-GP  [R402H16]  85.63 143.38 0 top
R1934  22R2J-2-GP  [R402H16]  56.68 166.75 90 top
R1935  10KR2J-3-GP  [R402H16]  162.09 54.61 90 bottom
R1953  0R2J-2-GP  [R402H16]  70.77 190.63 180 top
R1954  0R2J-2-GP  [R402H16]  72.3 191.01 270 top
R1980  0R2J-2-GP  [R402H16]  89.7 16.38 0 top
R1981  0R0402-PAD-2-GP  [0R0402-PAD-1]  90.71 16.38 0 top
R1984  0R0402-PAD-2-GP  [0R0402-PAD-1]  46.21 33.4 90 top
R1985  0R0402-PAD-2-GP  [0R0402-PAD-1]  43.59 25.78 0 top
R1986  10KR2J-3-GP  [R402H16]  85.76 211.07 0 bottom
R1987  10KR2J-3-GP  [R402H16]  73.44 208.03 180 bottom
R1988  10KR2J-3-GP  [R402H16]  72.04 211.33 90 bottom
R1989  1KR2F-3-GP  [R402H16]  70.01 211.33 270 bottom
R1993  0R2J-2-GP  [R402H16]  79.92 194.69 180 top
R1994  0R2J-2-GP  [R402H16]  82.96 194.69 180 top
R1995  0R2J-2-GP  [R402H16]  83.98 186.56 180 top
R1998  1KR2J-1-GP  [R402H16]  81.95 194.69 180 top
R1999  0R2J-2-GP  [R402H16]  82.84 196.85 90 top
R2000  1KR2J-1-GP  [R402H16]  85 186.56 180 top
R2001  0R2J-2-GP  [R402H16]  82.96 190.63 180 top
R2002  1KR2J-1-GP  [R402H16]  80.93 194.69 180 top
R2003  196R2F-GP  [R402H16]  60.1 174.24 180 top
R2004  2KR2J-1-GP  [R402H16]  56.8 158.62 270 top
R2008  2KR2J-1-GP  [R402H16]  56.8 155.57 270 top
R2010  10KR2J-3-GP  [R402H16]  56.8 154.56 90 top
R2012  10KR2J-3-GP  [R402H16]  56.8 157.61 90 top
R2013  10KR2J-3-GP  [R402H16]  144.43 39.12 0 top
R2014  10KR2J-3-GP  [R402H16]  145.45 39.12 0 top
R2017  0R0402-PAD-2-GP  [0R0402-PAD-1]  46.01 167 180 top
R2018  100KR2J-1-GP  [R402H16]  47.53 165.61 270 top
R2019  0R2J-2-GP  [R402H16]  49.56 165.61 270 top
R2021  0R2J-2-GP  [R402H16]  52.36 158.88 90 top
R2022  0R3J-0-U-GP  [R603H22]  77.76 194.31 0 top
R2023  0R2J-2-GP  [R402H16]  79.92 197.99 180 top
R2025  0R3J-0-U-GP  [R603H22]  76.49 194.31 180 top
R2026  0R2J-2-GP  [R402H16]  78.9 197.99 180 top
R2028  1KR2F-3-GP  [R402H16]  73.19 142.11 180 top
R2029  0R3J-0-U-GP  [R603H22]  39.28 119.51 0 top
R2030  0R3J-0-U-GP  [R603H22]  38.13 135.38 0 top
R2031  0R3J-0-U-GP  [R603H22]  39.4 135.38 0 top
R2032  0R3J-0-U-GP  [R603H22]  36.99 119.51 0 top
R2053  0R0402-PAD-2-GP  [0R0402-PAD-1]  62.39 135.76 0 top
R2054  0R0402-PAD-2-GP  [0R0402-PAD-1]  154.34 183.64 90 bottom
R2055  10KR2J-3-GP  [R402H16]  143.92 128.65 0 bottom
R2056  10KR2J-3-GP  [R402H16]  146.08 129.16 270 bottom
R2057  1KR2F-3-GP  [R402H16]  143.42 191.9 180 bottom
R2058  1KR2F-3-GP  [R402H16]  144.43 191.9 0 bottom
R2059  1KR2F-3-GP  [R402H16]  150.27 152.91 180 bottom
R2060  1KR2F-3-GP  [R402H16]  150.27 150.88 180 bottom
R2061  10KR2J-3-GP  [R402H16]  144.56 125.98 270 bottom
R2062  10KR2J-3-GP  [R402H16]  146.46 125.98 270 bottom
R2063  2KR2J-1-GP  [R402H16]  56.29 147.83 270 top
R2064  10KR2J-3-GP  [R402H16]  56.29 146.81 90 top
R2065  1KR2F-3-GP  [R402H16]  46.01 169.04 180 top
R2066  1KR2F-3-GP  [R402H16]  52.74 165.61 90 top
R2067  0R2J-2-GP  [R402H16]  69.43 152.43 180 bottom
R2077  10KR2J-3-GP  [R402H16]  28.99 30.73 90 bottom
R2078  0R2J-2-GP  [R402H16]  46.01 164.21 180 top
R2079  0R2J-2-GP  [R402H16]  31.53 74.93 180 top
R2080  0R0402-PAD-2-GP  [0R0402-PAD-1]  55.79 72.14 0 top
R2081  180R3F-GP  [R603H22]  128.28 44.37 90 top
R2082  4D3KR2F-GP  [R402H16]  130.71 41.54 180 top
R2083  2K2R2J-2-GP  [R402H16]  129.82 29.6 180 top
R2084  2K2R2J-2-GP  [R402H16]  130.83 29.6 180 top
R2085  4K7R2F-GP  [R402H16]  131.72 41.54 0 bottom
R2086  4K7R2F-GP  [R402H16]  132.87 29.6 0 top
R2087  4K7R2F-GP  [R402H16]  134.77 41.54 0 top
R2088  4K7R2F-GP  [R402H16]  132.74 41.54 0 top
R2089  4K7R2F-GP  [R402H16]  133.75 41.54 0 bottom
R2090  4K7R2F-GP  [R402H16]  132.74 41.54 0 bottom
R2091  10KR2J-3-GP  [R402H16]  124.24 28.7 0 top
R4230  0R2J-2-GP  [R402H16]  151.42 209.68 270 bottom
R4702  100KR2J-1-GP  [R402H16]  147.23 209.8 90 top
R4706  100KR2J-1-GP  [R402H16]  145.96 199.52 270 top
R4707  1K1R2F-GP  [R402H16]  152.05 215.9 270 bottom
R4708  1K1R2F-GP  [R402H16]  144.05 200.66 270 top
R6701  0R3J-0-U-GP  [R603H22]  75.09 68.35 90 top
R6702  10KR2J-3-GP  [R402H16]  76.11 63.63 180 top
R6703  100KR2J-1-GP  [R402H16]  79.87 63.98 180 top
R6704  100KR2J-1-GP  [R402H16]  77.5 66.6 180 top
R6705  100KR2J-1-GP  [R402H16]  83.4 68 270 top
R6706  0R2J-2-GP  [R402H16]  83.4 66.95 270 top
R79612  75R3F-GP  [R603H22]  65.29 12.27 270 top
R79618  0R2J-2-GP  [R402H16]  80.68 29.08 90 top
R79619  1R5J-2-GP  [R805H24]  38.51 42.93 180 bottom
R79621  10KR2F-2-GP  [R402H16]  44.31 35.48 90 top
R79622  D33R6F-GP  [R1206H26]  49.13 46.58 270 bottom
R79623  300KR2F-GP  [R402H16]  41.33 33.55 270 top
R79625  10KR2F-2-GP  [R402H16]  42.58 31.62 0 top
R79627  300KR2F-GP  [R402H16]  40.42 36.98 270 top
R79628  100KR2F-L1-GP  [R402H16]  35.72 32.03 0 top
R79630  200R5J-GP  [R805H24]  47.81 43.61 180 bottom
R79631  0R1206-PAD-1-GP  [0R1206-PAD-1]  50.45 47.22 270 top
R79633  0R0402-PAD-2-GP  [0R0402-PAD-1]  39.73 32.03 0 top
R79634  0R0402-PAD-2-GP  [0R0402-PAD-1]  38.69 32.03 0 top
R79635  10KR2J-3-GP  [R402H16]  85 135.76 0 top
R79637  10KR2J-3-GP  [R402H16]  151.42 41.15 0 top
R79638  10KR2J-3-GP  [R402H16]  153.07 41.15 0 top
R79639  0R0402-PAD-2-GP  [0R0402-PAD-1]  134.9 29.6 0 top
R79640  0R0402-PAD-2-GP  [0R0402-PAD-1]  135.91 29.6 0 top
R79643  0R5J-5-GP  [R805H24]  59.6 43.69 90 bottom
R79644  0R5J-5-GP  [R805H24]  59.6 45.85 270 top
R79645  0R5J-5-GP  [R805H24]  59.6 39.62 90 bottom
R79646  0R5J-5-GP  [R805H24]  59.6 45.72 90 bottom
R79647  0R2J-2-GP  [R402H16]  35.21 60.33 270 top
R79648  0R2J-2-GP  [R402H16]  35.21 59.31 270 top
R79649  0R2J-2-GP  [R402H16]  157.64 87.5 90 top
R79650  10KR2J-3-GP  [R402H16]  62.26 153.67 270 top
R79651  10KR2J-3-GP  [R402H16]  56.8 167.77 270 top
R79652  10KR2J-3-GP  [R402H16]  77.25 142.11 0 top
R79653  10KR2J-3-GP  [R402H16]  86.14 152.96 270 bottom
R79654  10KR2J-3-GP  [R402H16]  79.66 149.22 90 bottom
R79655  0R3J-0-U-GP  [R603H22]  159.93 142.75 0 top
R79656  0R5J-5-GP  [R805H24]  59.6 41.66 90 bottom
R79657  0R2J-2-GP  [R402H16]  77.93 65.02 90 top
R79658  0R2J-2-GP  [R402H16]  79.15 66.14 90 top
R79659  10KR2J-3-GP  [R402H16]  42.6 113.89 180 top
R79661  1KR2F-3-GP  [R402H16]  41.56 113.92 0 top
R79662  100KR2J-1-GP  [R402H16]  103.16 121.67 0 top
R79663  10KR2J-3-GP  [R402H16]  100.11 121.67 0 top
R79664  10KR2J-3-GP  [R402H16]  93.38 115.06 90 top
R79665  100KR2J-1-GP  [R402H16]  104.17 121.67 180 top
R79666  470KR2F-GP  [R402H16]  102.14 121.67 180 top
R79667  1MR2J-1-GP  [R402H16]  101.13 121.67 0 top
R79668  100KR2J-1-GP  [R402H16]  76.36 66.6 0 top
R79669  0R2J-2-GP  [R402H16]  142.91 56.77 270 bottom
R79670  10KR2J-3-GP  [R402H16]  86.01 135.76 0 top
R79671  10KR2J-3-GP  [R402H16]  56.8 153.54 270 top
R79672  10KR2J-3-GP  [R402H16]  81.31 143.51 0 top
R79673  10KR2J-3-GP  [R402H16]  56.8 170.81 270 top
R79674  0R2J-2-GP  [R402H16]  151.42 210.69 270 bottom
R79675  100KR2J-5-GP  [R402H16]  151.42 211.71 270 bottom
R79676  10KR2J-3-GP  [R402H16]  150.27 44.07 270 bottom
R79677  10KR2J-3-GP  [R402H16]  150.27 45.09 270 bottom
R79678  10KR2J-3-GP  [R402H16]  70.9 151 270 bottom
R79679  10KR2J-3-GP  [R402H16]  70.9 153.03 270 bottom
R79680  10KR2J-3-GP  [R402H16]  70.9 152.02 270 bottom
R79681  10KR2J-3-GP  [R402H16]  65.06 138.94 90 top
R79682  33R2J-2-GP  [R402H16]  68.99 139.7 270 top
R79683  33R2J-2-GP  [R402H16]  66.58 139.83 180 top
R79684  33R2J-2-GP  [R402H16]  65.06 137.92 90 top
R79685  33R2J-2-GP  [R402H16]  63.53 138.43 180 top
R79686  0R0402-PAD-2-GP  [0R0402-PAD-1]  148.88 64.26 0 top
R79687  10KR2J-3-GP  [R402H16]  150.91 64.26 180 top
R79688  10KR2J-3-GP  [R402H16]  151.93 64.26 180 top
R79689  10KR2J-3-GP  [R402H16]  162.09 53.59 270 bottom
R79690  10KR2J-3-GP  [R402H16]  162.09 55.63 270 bottom
R79691  0R2J-2-GP  [R402H16]  154.08 41.15 180 top
R79692  1KR2J-1-GP  [R402H16]  90.97 121.03 0 top
R79693  1KR2J-1-GP  [R402H16]  86.39 118.49 180 top
R79694  10KR2J-3-GP  [R402H16]  86.39 120.4 180 top
R79697  0R2J-2-GP  [R402H16]  107.6 53.09 90 top
R79698  0R2J-2-GP  [R402H16]  115.48 50.42 180 top
R79699  0R2J-2-GP  [R402H16]  116.49 50.42 180 top
R79700  0R2J-2-GP  [R402H16]  114.46 50.42 180 top
R79701  0R2J-2-GP  [R402H16]  110.14 50.8 90 top
R79702  0R2J-2-GP  [R402H16]  110.14 51.82 90 top
R79703  0R2J-2-GP  [R402H16]  110.14 52.83 90 top
R79704  0R2J-2-GP  [R402H16]  108.87 48.64 180 bottom
R79705  10KR2F-2-GP  [R402H16]  103.67 60.58 270 bottom
R79706  10KR2F-2-GP  [R402H16]  101.76 60.58 270 bottom
R79707  0R3J-0-U-GP  [R603H22]  103.79 54.61 0 top
R79708  0R0402-PAD-2-GP  [0R0402-PAD-1]  111.41 63.37 270 top
R79709  0R2J-2-GP  [R402H16]  93.89 50.04 90 bottom
R79710  0R2J-2-GP  [R402H16]  95.16 48.9 270 bottom
R79711  0R2J-2-GP  [R402H16]  109.51 54.23 90 bottom
R79712  0R2J-2-GP  [R402H16]  94.39 57.66 270 bottom
R79713  0R2J-2-GP  [R402H16]  109.63 55.5 90 bottom
R79714  10KR2J-3-GP  [R402H16]  84.87 145.54 180 bottom
R79720  100KR2F-L1-GP  [R402H16]  108.11 60.58 270 bottom
R79721  33KR2J-3-GP  [R402H16]  108.11 61.72 90 bottom
R79722  100KR2F-L1-GP  [R402H16]  109.89 58.04 180 top
R79723  10KR2F-2-GP  [R402H16]  109.89 56.13 180 top
R79724  0R2J-2-GP  [R402H16]  147.86 200.66 90 top
R79725  0R2J-2-GP  [R402H16]  145.96 200.66 90 top
R79726  10KR5F-2-GP  [R805H24]  33.05 20.57 90 bottom
R79727  10KR2J-3-GP  [R402H16]  102.14 126.49 90 top
R80201  4K7R2J-2-GP  [R402H16]  25.05 10.29 0 bottom
R80202  4K7R2J-2-GP  [R402H16]  26.07 10.29 0 bottom
R80206  0R2J-2-GP  [R402H16]  147.73 44.07 0 bottom
R80207  0R2J-2-GP  [R402H16]  150.27 41.15 180 top
R80208  0R2J-2-GP  [R402H16]  147.73 39.5 90 top
R80209  0R2J-2-GP  [R402H16]  147.23 41.02 180 top
R80210  0R2J-2-GP  [R402H16]  146.21 41.02 180 top
R80211  0R2J-2-GP  [R402H16]  145.19 41.02 180 top
R80212  10KR2J-3-GP  [R402H16]  102.27 56.64 0 top
R80213  0R2J-2-GP  [R402H16]  106.59 41.15 180 top
R80215  15KR2F-GP  [R402H16]  139.48 43.43 90 top
R80216  10KR2F-2-GP  [R402H16]  141.64 43.81 0 bottom
R80217  10KR2J-3-GP  [R402H16]  157.77 43.56 180 bottom
R80218  10KR2J-3-GP  [R402H16]  158.28 41.78 270 bottom
R80219  0R2J-2-GP  [R402H16]  140.75 64.39 180 bottom
R80220  0R2J-2-GP  [R402H16]  139.73 64.39 180 bottom
R80221  10KR2J-3-GP  [R402H16]  162.21 48.51 90 top
R80222  10KR2J-3-GP  [R402H16]  162.21 49.53 90 top
R80223  0R2J-2-GP  [R402H16]  162.09 46.48 270 top
R80224  0R2J-2-GP  [R402H16]  146.85 61.47 270 bottom
R80225  0R0402-PAD-2-GP  [0R0402-PAD-1]  72.3 189.99 270 top
R80226  0R2J-2-GP  [R402H16]  157.89 49.78 180 bottom
R80227  0R2J-2-GP  [R402H16]  20.73 164.47 180 top
R80228  8K2R2J-3-GP  [R402H16]  88.93 55.24 270 bottom
R80229  39K2R2F-L-GP  [R402H16]  87.28 54.74 180 bottom
R80230  10KR2J-3-GP  [R402H16]  92.62 51.56 0 bottom
R80231  0R2J-2-GP  [R402H16]  155.23 64.14 180 top
R80232  0R2J-2-GP  [R402H16]  164.24 56.13 0 top
R80233  10KR2J-3-GP  [R402H16]  41.56 116.97 270 bottom
RJ1  RJ45-8P-199-GP  [23-01120-2A03-A]  76.92 21.04 180 top
RN7  SRN10KJ-6-GP  [ARES8-CN24-MUH20]  154.59 56.01 0 bottom
RN8  SRN10KJ-5-GP  [ARES2H18]  147.35 64.77 180 top
RN9  SRN10KJ-5-GP  [ARES2H18]  142.27 64.77 180 top
RN10  SRN10KJ-6-GP  [ARES8-CN24-MUH20]  146.46 53.47 90 bottom
RN12  SRN1KJ-8-GP  [SMD-ARES8-1H26]  96.43 209.17 0 bottom
RN13  SRN33J-7-GP-U  [ARES8-CN24-UH20]  153.45 52.7 180 bottom
RN16  SRN2K2J-1-GP  [ARES2H16]  100.74 96.39 0 top
RN4301  SRN33J-7-GP-U  [ARES8-CN24-UH20]  35.21 65.15 270 bottom
RT1  NTC-10K-19-GP-U  [NTC-402H22-U]  100.11 172.85 180 top
RT2  NTC-10K-19-GP-U  [NTC-402H22-U]  85.76 85.52 0 top
RT3  NTC-10K-19-GP-U  [NTC-402H22-U]  18.19 190.5 180 top
RV1  P4500SCLHLRP-GP  [TVS5436-1121H105]  65.06 18.8 0 top
SATAP1  CLX-CON5-18-GP-U  [CI2505P1H00-LF-U]  12 195 270 top
SPI1  MX25L6406EM2I-12G-GP  [SOIC8-1H86]  35.09 127.25 180 top
SPK1  JWT-CON6-20-GP  [A1501WV0-6PS-5E]  147.84 14.27 180 top
SPR1  SPRING-62-GP  [SPR10637H367]  165.4 172.7 270 top
SRCON1  SKT-SPI8P-GP-U1  [SKT-SOIC8-092117H235]  35.09 127.25 0 top
SSUSB1  SKT-USB11-112-GP-U  [SKT-USB11-138165-1]  176.12 116.84 90 top
SSUSB2  SKT-USB11-112-GP-U  [SKT-USB11-138165-1]  176.12 95.34 90 top
TC1  ST330U2D5VDM-9GP  [CT7343H75]  133.76 204.09 270 bottom
TC7  E100U16VM-47-GP  [ECAP-100D6D3H237]  107.48 24.51 270 top
TC8  E100U16VM-47-GP  [ECAP-100D6D3H237]  166.91 101.6 0 top
TC21  E820U2D5VM-7-GP  [ECAP-100D6D3H355]  59.34 77.34 270 top
TOUCH1  ENT-CON5-GP  [3703K-Q05N-11L]  24.7 8.5 270 top
TP6  -  [TPAD28]  74.33 175.39 180 bottom
TP8  -  [TPAD28]  73.44 150.37 180 bottom
TP9  -  [TPAD28]  74.91 162.71 180 bottom
TP24  -  [TPAD28]  157.77 35.81 180 top
TP25  -  [TPAD28]  155.23 42.8 270 top
TP26  -  [TPAD28]  153.96 42.8 270 top
TP28  -  [TPAD28]  140.88 46.23 270 top
TP37  -  [TPAD28]  88.81 156.21 180 bottom
TP38  -  [TPAD28]  121.32 215.26 0 top
TP39  -  [TPAD28]  122.59 215.26 0 top
TP62  -  [TPAD28]  107.22 208.03 0 top
TP63  -  [TPAD28]  122.59 207.65 0 top
TP64  -  [TPAD28]  121.32 207.65 0 top
TP65  -  [TPAD28]  121.32 212.72 0 top
TP66  -  [TPAD28]  122.59 212.72 0 top
TP67  -  [TPAD28]  121.32 214 0 top
TP68  -  [TPAD28]  122.59 211.46 0 top
TP69  -  [TPAD28]  121.32 211.46 0 top
TP70  -  [TPAD28]  122.59 210.19 0 top
TP71  -  [TPAD28]  121.32 210.19 0 top
TP72  -  [TPAD28]  122.59 208.91 0 top
TP73  -  [TPAD28]  121.32 208.91 0 top
TP74  -  [TPAD28]  105.95 208.03 0 top
TP75  -  [TPAD28]  104.68 208.03 0 top
TP76  -  [TPAD28]  107.22 209.93 0 top
TP77  -  [TPAD28]  105.95 209.93 0 top
TP78  -  [TPAD28]  104.68 209.93 0 top
TP79  -  [TPAD28]  105.95 220.47 0 top
TP80  -  [TPAD28]  107.22 220.47 0 top
TP81  -  [TPAD28]  105.95 222.12 0 top
TP82  -  [TPAD28]  107.22 222.12 0 top
TP83  -  [TPAD28]  105.95 223.77 0 top
TP84  -  [TPAD28]  107.22 223.77 0 top
TP149  -  [TPAD28]  83.98 85.85 0 top
TP150  -  [TPAD28]  83.98 84.58 0 top
TP155  -  [TPAD28]  81.34 85.83 0 top
TP158  -  [TPAD28]  81.21 89.9 180 bottom
TP159  -  [TPAD28]  88.58 98.02 180 bottom
TP163  -  [TPAD28]  97.19 96.77 0 top
TP164  -  [TPAD28]  97.19 95.38 0 top
TP165  -  [TPAD28]  97.19 94.11 0 top
TP174  -  [TPAD28]  73.06 175.26 180 bottom
TP175  -  [TPAD28]  90.2 156.21 180 bottom
TP176  -  [TPAD28]  89.82 171.83 180 bottom
TP177  -  [TPAD28]  89.36 173.33 180 bottom
TP178  -  [TPAD28]  90.08 154.94 180 bottom
TP179  -  [TPAD28]  76.94 165.28 180 bottom
TP180  -  [TPAD28]  75.55 166.42 180 bottom
TP181  -  [TPAD28]  75.85 188.34 0 top
TP182  -  [TPAD28]  77 188.98 0 top
TP183  -  [TPAD28]  78.01 188.21 0 top
TP184  -  [TPAD28]  90.71 173.61 180 bottom
TP186  -  [TPAD28]  77.12 143.76 0 top
TP187  -  [TPAD28]  79.51 150.47 180 bottom
TP188  -  [TPAD28]  74.33 48.01 90 bottom
TP189  -  [TPAD28]  75.85 50.85 0 top
TP190  -  [TPAD28]  68.87 141.1 0 top
TP192  -  [TPAD28]  82.25 178.92 180 bottom
TP193  -  [TPAD28]  79.79 180.85 180 bottom
TP194  -  [TPAD28]  78.21 179.55 180 bottom
TP195  -  [TPAD28]  81.41 180.57 180 bottom
TP196  -  [TPAD28]  122.59 214 0 top
TP198  -  [TPAD28]  77 158.12 180 bottom
TP199  -  [TPAD28]  76.11 155.19 180 bottom
TP203  -  [TPAD28]  120.94 80.39 270 top
TP204  -  [TPAD28]  120.48 68.91 90 bottom
TP208  -  [TPAD28]  123.73 222.5 0 top
TP210  -  [TPAD28]  95.16 174.12 180 bottom
TP211  -  [TPAD28]  96.76 173.69 180 bottom
TP212  -  [TPAD28]  100.62 155.83 0 top
TP213  -  [TPAD28]  89.82 174.88 180 bottom
TP214  -  [TPAD28]  76.61 163.91 180 bottom
TP215  -  [TPAD28]  140.88 53.09 0 top
TP4124  -  [TPAD28]  95.54 56.52 180 bottom
TP4125  -  [TPAD28]  94.27 56.52 180 bottom
TP4126  -  [TPAD28]  93 53.98 180 bottom
TP4127  -  [TPAD28]  94.27 53.98 180 bottom
TP4128  -  [TPAD28]  95.54 53.98 180 bottom
TP4129  -  [TPAD28]  94.27 55.24 180 bottom
TP4130  -  [TPAD28]  95.54 55.24 180 bottom
TR1  FILTER-4P-137-GP  [L125100-4P-1H28]  153.07 197.61 180 top
TR3  FILTER-4P-137-GP  [L125100-4P-1H28]  164.24 108.71 180 top
TR4  FILTER-4P-137-GP  [L125100-4P-1H28]  164.24 106.55 180 top
TR9  MCM1012B900FBP-GP-U  [L125100-4P-1H37]  31.78 13.34 90 top
TR10  FILTER-4P-137-GP  [L125100-4P-1H28]  95.11 33.91 90 top
TR12  MCM1012B900FBP-GP-U  [L125100-4P-1H37]  106.21 206.25 180 top
TR14  FILTER-4P-137-GP  [L125100-4P-1H28]  92.82 33.91 90 top
TR16  FILTER-4P-120-GP  [L125100-4P-1H28]  126.78 32.27 0 top
TR17  FILTER-4P-120-GP  [L125100-4P-1H28]  126.78 34.43 0 top
TR18  FILTER-4P-120-GP  [L125100-4P-1H28]  126.78 36.71 0 top
TR19  FILTER-4P-120-GP  [L125100-4P-1H28]  126.78 38.87 0 top
U1  AO6402A-GP  [SOT-6-1H50]  32.16 109.17 0 bottom
U2  AO4468L-GP  [SOIC8H69]  48.17 141.1 0 top
U3  AZ1045-04F-R7G-GP  [DFN10G2510H26]  168.94 116.84 270 top
U5  AZ1045-04F-R7G-GP  [DFN10G2510H26]  168.94 95.38 270 top
U6  ALC3661-CG-GP  [QFN48J6-G465H40]  162.59 78.23 0 top
U7  MX25L1006EMI-10G-GP  [SOIC8H69]  125.46 48.51 90 top
U9  ISL62882CHRTZ-T-GP  [QFN40-G3D5H32]  121.06 74.55 180 top
U10  AZC099-04S-1-GP  [SOT-6H58]  47.2 11.94 270 top
U11  AZC099-04S-1-GP  [SOT-6H58]  47.2 11.94 270 bottom
U12  AZC099-04S-1-GP  [SOT-6H58]  77.25 29.08 270 top
U16  RTL8111G-CGT-1-GP-U2  [QFN32J4-G2D85H36]  37.88 14.86 270 top
U21  TPA3131D2RHBR-GP-U  [QFN32-G3D55H40]  155.35 30.61 270 top
U25  M24C64-WMN6TP-2-GP  [SOIC8H69]  38.01 81.79 180 bottom
U26  RTD2136S-CG-GP  [QFN48J6-G4D55H40]  37.78 94.5 270 bottom
U31  AZ1045-04F-R7G-GP  [DFN10G2510H26]  123.48 37.36 90 top
U42  AO6402A-GP  [SOT-6-1H50]  110.52 88.01 180 top
U49  PM25LD010C-SCE-1-GP  [SOIC8H69]  102.78 81.92 90 top
U52  TPS22966DPUR-GP  [SON14J3020-G2610H34]  145.63 7.04 90 top
U54  TPS22966DPUR-GP  [SON14J3020-G2610H34]  90.33 11.81 0 top
U55  BQ24727RGRR-1-GP  [QFN20G3D5-G2D15H40]  60.74 56.26 180 bottom
U105  AO6402A-GP  [SOT-6-1H50]  43.47 131.19 270 top
U109  IT8739E-GP  [LQFP128H63]  150.66 52.58 270 top
U110  AO4407AL-GP  [SOIC8H69]  66.33 38.99 0 top
U116  AZ1045-04F-R7G-GP  [DFN10G2510H26]  123.48 33.78 270 top
U117  AZ1045-04F-R7G-GP  [DFN10G2510H26]  123.48 40.89 270 top
U118  PS8407ATQFN40GTR2-A1-GP  [QFN40J5-G3D65H32]  132.74 35.57 270 top
U119  AZ1117CR-ADJTRG1-GP-U  [SOT-89-4541-3PH63]  131.45 46.74 90 bottom
U120  OZ554ALN-B-0-TR-GP  [QFN20-G2D1H32]  37.37 36.58 90 bottom
U178  TS3702IDT-GP  [SOIC8H69]  147.35 204.85 0 top
U4101  NPCE948LA0DX-GP  [LQFP64H63]  102.27 54.48 0 bottom
U6701  KXCNL-1010-GP  [LGA16G3-1H40]  79.03 69.9 0 top
U6702  AO4468L-GP  [SOIC8H69]  95.66 123.19 0 top
UHS1  AUDIO-JK500-GP  [2SJ3082-038111F]  176.5 75.29 90 top
UR5  330R2F-GP  [R402H16]  80.68 28.07 90 top
UR6  330R2F-GP  [R402H16]  73.69 30.1 270 top
UR7  330R2F-GP  [R402H16]  73.69 29.08 270 top
USB3  SKT-USB6-174-GP  [SKT-USB6-135063]  98.35 37.03 90 top
USB4  SKT-USB6-174-GP  [SKT-USB6-135063]  98.35 14.03 90 top
WEBCM1  JWT-CON8-4-GP  [A1251WR0-8PS-5E]  160.12 201.1 180 top
X1  XTAL-48MHZ-27-GP-U  [OSC-3225-4P-4H36]  62.52 172.85 90 top
X2  XTAL-32D768KHZ-67-GP  [SMD49-6914-0403H56]  59.72 150.88 180 top
X4  XTAL-25MHZ-181-GP  [OSC-3225-4P-4H36]  36.74 6.86 0 top
X5  XTAL-27MHZ-85-GP-U  [OSC-3225-4P-4H30]  101 110.11 90 top
XF1  XFORM-12P-48-GP  [XFORM12A127097H91]  56.29 11.94 90 top
XF2  XFORM-12P-48-GP  [XFORM12A127097H91]  56.29 11.94 270 bottom

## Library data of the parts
AFTP1 = AFTE14P-75: tolerance: ZZ.AFT14.101
BAT2 = 50290-0100N-001: tolerance: 20.F2196.010
BT1 = AAA-BAT-034-K01: tolerance: 62.70010.031
BTRST1 PSWD1 = A2541WV0-1EX2PA-6T: tolerance: 21.60909.102
C1 C6 C41 C42 C44-C46 C60 C84 C91 C101 C103 C111 C113 C122 C131 C145 C147 C163 C186 C197 C204 C211 C213 C214 C216 C231 C238 C284 C289 C290 C293 C295 C297-C305 C316 C337 C353 C392 C483 C486 C489 C495 C500 C514 C529 C540 C549 C550 C557-C559 C570 C572 C574 C582-C585 C587 C595 C612 C616 C623 C627 C714 C721 C774 C781 C789-C792 C820 C821 C826 C829 C853 C869 C1609 C1617 C1701 C1723 C1731 C1732 C1737 C1742 C1746 C1753 C1754 C1757 C1758 C1769 C1805 C1806 C1808-C1818 C1820 C1826 C1832 C1834 C1838-C1845 C1851-C1854 C1856 C1857 C1859-C1861 C1868 C1869 C1877 C1926 C1961 C1966-C1970 C1977 C1979 C1982 C3366 C3368-C3375 C3377-C3379 C3382 C3383 C3453 C3454 C6701 C6702 C6708 C6709 C6711 C6717 C6721 PC96 PC151 PC4607 PC4619 PC4802 PC5213 PC5433 = C402H22: tolerance: 78.10421.2FLDL
C2 C3 C72 C109 C127 C129 C474 C478 C485 C1674 C1677 C1695 C1702 C1704-C1707 C1714 C1715 C1743 C1744 C1858 C6710 C6714 C6715 = C603H36: tolerance: 78.10610.5BLDL
C4 C20 = C603H36: tolerance: 78.47523.5BLDL
C5 = C603H36: tolerance: 78.47422.5BLDL
C7 C9 C11 C100 C170 C591 C593 C863 C864 C866 C871 C1616 C1739 C1798 C1827 C1957 C6716 = C402H22: tolerance: 78.10523.5FL
C8 C15 C65 C1608 C1727 C1836 C1837 C1928 C1929 C1959 C1980 C1981 PC7 PC57 PC4601 PC4605 PC4606 PC4618 PC4622 PC4706 PC4712 PC4804 PC4807 PC5003 PC5235 PC5405 PC5413 PC5414 PC5418 = C402H22: tolerance: 78.10224.2FLDL
C10 C134 C157 C159 C160 C194 C203 C267 C268 C1780 C6722 PC5244 = C402H22: tolerance: 78.10134.1FLDL
C14 C114 C115 C118 C119 C141 C142 C149 C151 C207 C755 C1764 C1850 C1855 C1864 C1870 C3376 C3380 C3381 C3452 C3457 C3458 C6704 PC73 PC4609 PC4614 PC4616 PC4901 PC4905 PC5232 = C402H22: tolerance: 78.10324.2FLDL
C32 = C603H36: tolerance: 78.10492.4BLLL
C33 = C402H22: tolerance: 78.27034.1FLLL
C35 = C603H36: tolerance: 78.33135.1BL
C36-C39 = C1206H75: tolerance: 078.10525.022D
C40 = C1206H71: tolerance: 78.10525.22LLL
C43 C3456 = C402H22: tolerance: 78.10422.5FLLL
C48 C543 C551 C3459 C3460 PC4401 PC4406 PC4407 PC5240 PC5241 = C805H58: tolerance: 78.10622.51LDL
C50 C52 = C402H22: tolerance: 78.5R674.1FLDL
C55 C138 C139 C771 C780 C784 C787 C788 C797 C804 C810 C811 C828 C830 C1724 C1725 C1971-C1973 PC4914 = C603H36: tolerance: 78.47520.5BLDL
C57 PC4301 PC4305 PC4612 PC4627 PC5416 = C402H22: tolerance: 78.10034.1FLDL
C58 = C402H22: tolerance: 78.8R064.1FLDL
C61 C77 C1735 = C402H22: tolerance: 78.10322.2FL
C66 C121 C132 C1733 C1734 = C402H22: tolerance: 78.10134.1FL
C67 = C402H22: tolerance: 78.10321.2FL
C73 C202 C209 C1803 C1804 = C603H36: tolerance: 78.47520.5BL
C74 C87 C88 C106 C516 C580 C763 C764 C1729 C1730 C1747 C1760 C1930 C1975 C1976 = C402H22: tolerance: 78.10421.2FL
C75 C140 C579 C1615 C1745 C1802 PC12 PC4608 = C603H36: tolerance: 78.22523.5BLDL
C76 C1738 PC6 = C402H22: tolerance: 78.15134.1FLDL
